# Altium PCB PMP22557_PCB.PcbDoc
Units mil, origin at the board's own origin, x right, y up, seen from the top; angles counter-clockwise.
Board outline 2244.09 x 866.14 mil, 2 copper layers (Top Layer, Bottom Layer), stack 62 mil thick; 30 components, 13 nets, 58 pads, 57 vias.
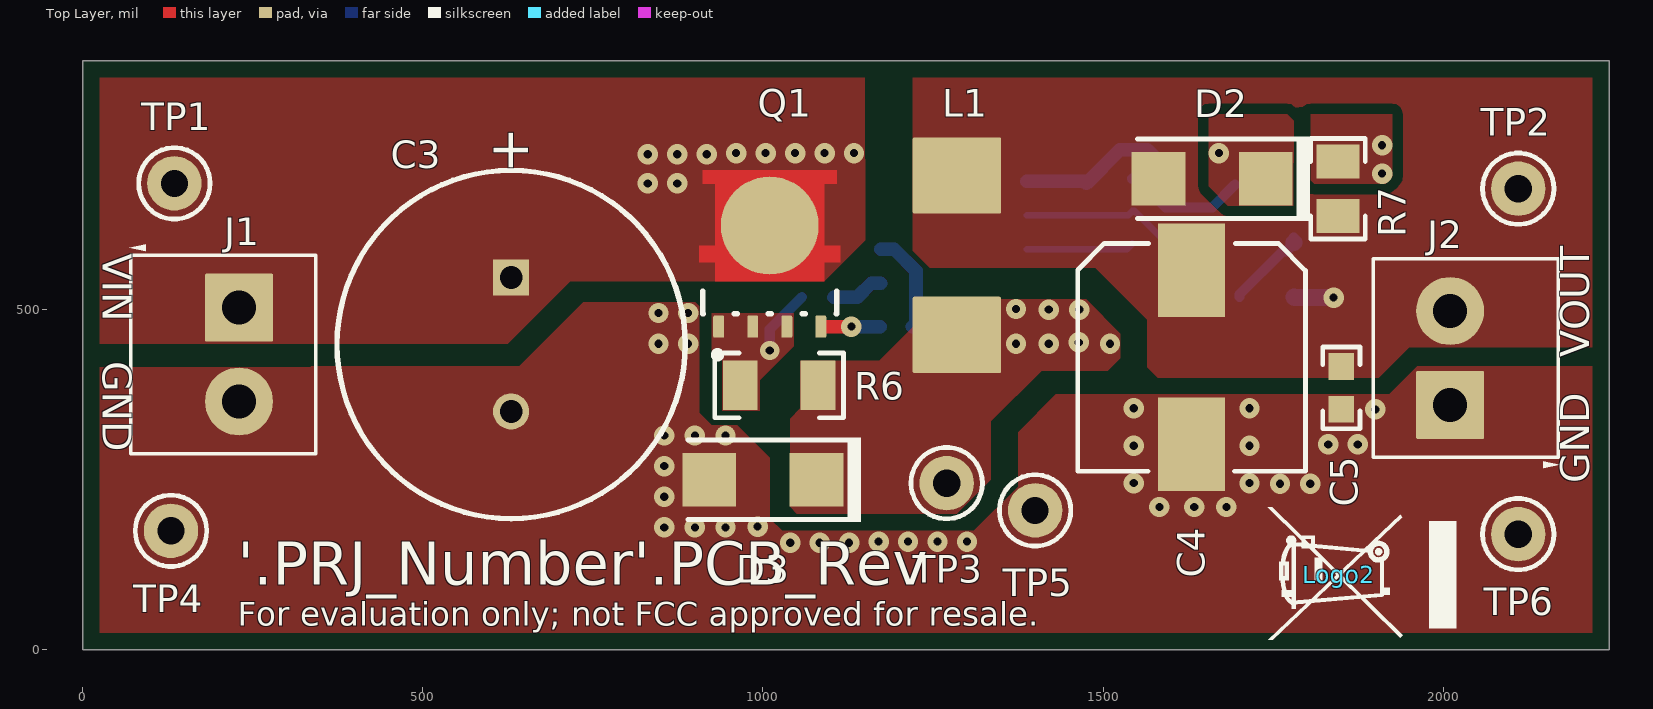
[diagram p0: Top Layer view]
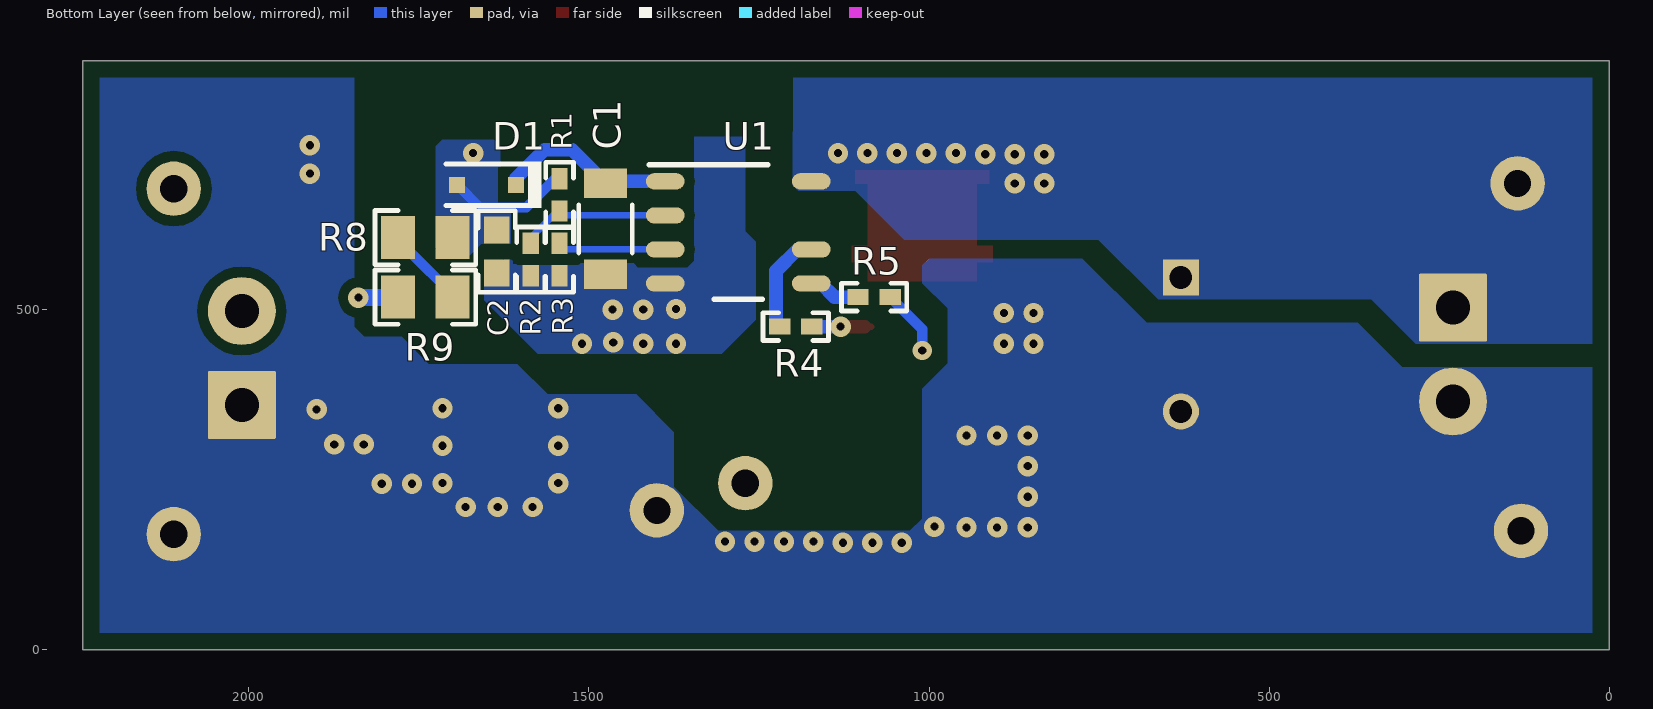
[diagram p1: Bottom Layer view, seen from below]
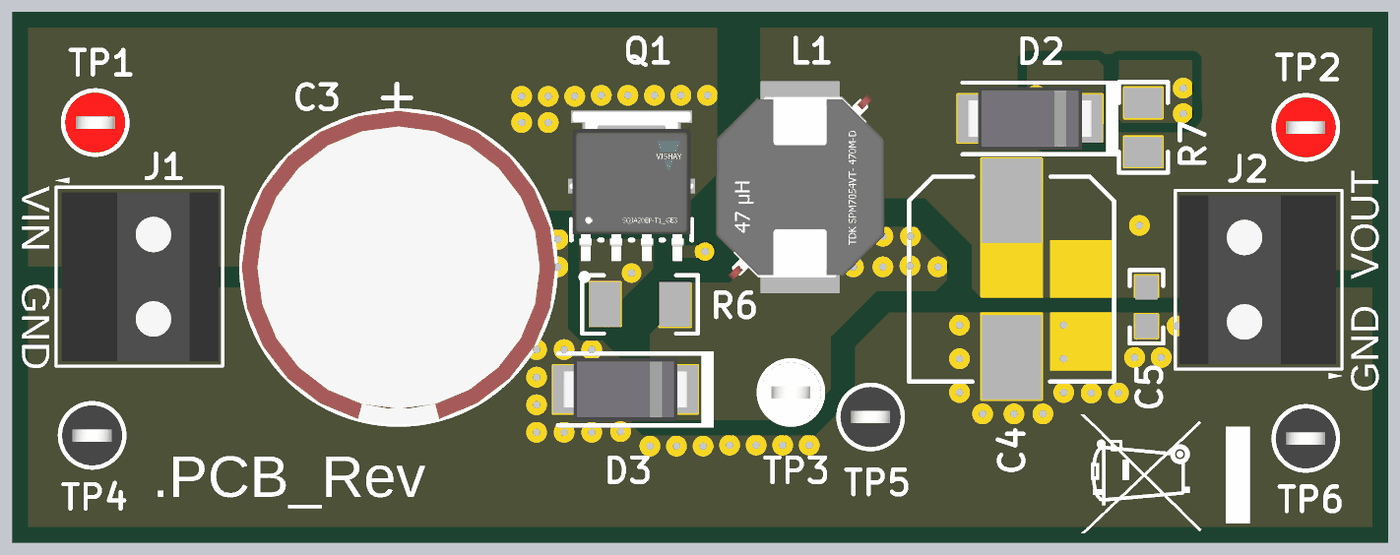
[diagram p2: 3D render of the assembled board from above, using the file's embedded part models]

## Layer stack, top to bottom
Top Solder: solder mask 0.4, Solder Resist, Dk 3.5
Top Layer: signal copper 1.4
Dielectric1: core 59.2, FR-4, Dk 4.8
Bottom Layer: signal copper 1.4
Bottom Solder: solder mask 0.4, Solder Resist, Dk 3.5

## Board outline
0,0 2244.09,0 2244.09,866.14 0,866.14

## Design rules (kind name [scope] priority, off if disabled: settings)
AcuteAngle [All] p1: minimum=4.50000000000000E+0001 checktracksonly=FALSE
AssemblyTestPointUsage [All] p1: valid=2
BoardOutlineClearance BoardOutlineClearance_MountingHoles [OnCopper and InComponentClass('Mounting Holes')] p1: gap=39.37 ignorepadtopadclearanceinfootprint=FALSE
BoardOutlineClearance BoardOutlineClearance_Poly [OnCopper and IsPoly] p2: gap=25 ignorepadtopadclearanceinfootprint=FALSE
BoardOutlineClearance [OnCopper and Not InComponentClass('Logo') and not InComponentClass('FiducialMark') and not InRegion(1000,500,4000,800) and not InPoly] p3: gap=30 ignorepadtopadclearanceinfootprint=FALSE
Clearance Clearance_Keepouts [((IsTrack Or IsArc) And Not InPoly) And IsFree and IsKeepOut vs ((IsTrack Or IsArc) And Not InPoly) And IsFree and IsKeepOut] p1: gap=0 ignorepadtopadclearanceinfootprint=FALSE
Clearance Clearance_Poly [InPolygon] p2: gap=15 ignorepadtopadclearanceinfootprint=TRUE
Clearance Clearance_FiducialMark [IsKeepOut and InComponentClass('FiducialMark') vs IsPad and InComponentClass('FiducialMark')] p3: gap=0 ignorepadtopadclearanceinfootprint=FALSE
Clearance [All] p4: gap=7.87 ignorepadtopadclearanceinfootprint=TRUE
ComponentClearance ComponentClearance_MountingHoles_FiducialMarks [InComponentClass('Mounting Holes') vs InComponentClass('FiducialMark')] p1: gap=50 collisioncheckmode=3 verticalgap=10 showdistances=FALSE
ComponentClearance ComponentClearance_Shunt [InComponentClass('Header') vs InComponentClass('Shunt')] p2: gap=0 collisioncheckmode=3 verticalgap=0 showdistances=FALSE
ComponentClearance ComponentClearance_Logo [InComponentClass('Logo')] p3: gap=50 collisioncheckmode=3 verticalgap=10 showdistances=FALSE
ComponentClearance ComponentClearance_ScrewToNut [(HasFootprint('NY PMS 440 0025 PH')) vs (HasFootprint('Keystone_1902C'))] p4: gap=5 collisioncheckmode=3 verticalgap=10 showdistances=FALSE
ComponentClearance ComponentClearance_MountingHoles [InComponentClass('Mounting Holes')] p5: gap=250 collisioncheckmode=3 verticalgap=100000 showdistances=FALSE
ComponentClearance ComponentClearance_SmallPassives [HasFootprint('0201*') or HasFootprint('0402*') or HasFootprint('0508') or HasFootprint('0603*') or HasFootprint('0612') or HasFootprint('0805*') or HasFootprint('0815*') or HasFootprint('0830*') or HasFootprint('1206*') or HasFootprint('1210*') or HasFootprint('1808*') or HasFootprint('1812*') or HasFootprint('1825*') or HasFootprint('2010*') or HasFootprint('2220*') or HasFootprint('2225*') or HasFootprint('2512*') or HasFootprint('2728*') or HasFootprint('3518*') vs HasFootprint('0201*') or HasFootprint('0402*') or HasFootprint('0508') or HasFootprint('0603*') or HasFootprint('0612') or HasFootprint('0805*') or HasFootprint('0815*') or HasFootprint('0830*') or HasFootprint('1206*') or HasFootprint('1210*') or HasFootprint('1808*') or HasFootprint('1812*') or HasFootprint('1825*') or HasFootprint('2010*') or HasFootprint('2220*') or HasFootprint('2225*') or HasFootprint('2512*') or HasFootprint('2728*') or HasFootprint('3518*')] p6: gap=14.96 collisioncheckmode=3 verticalgap=10 showdistances=FALSE
ComponentClearance ComponentClearance_THtoSMT [IsThruComponent vs IsSMTComponent] p7: gap=30 collisioncheckmode=3 verticalgap=30 showdistances=FALSE
ComponentClearance ComponentClearance_THtoTH [IsThruComponent vs IsThruComponent] p8: gap=30 collisioncheckmode=3 verticalgap=30 showdistances=FALSE
ComponentClearance [All] p9: gap=20 collisioncheckmode=3 verticalgap=10 showdistances=FALSE
DiffPairsRouting [All] p1: maxlimit=100 minlimit=10 mostfreqgap=10 toplayer_minwidth=15 toplayer_maxwidth=15 toplayer_prefwidth=15 bottomlayer_minwidth=15 bottomlayer_maxwidth=15 bottomlayer_prefwidth=15 maxuncoupledlength=1000
FabricationTestPointUsage TestPointUsage [All] p1: valid=2 allowmultiple=FALSE
FabricationTestpoint Testpoint [All] p1: side=3 testpointundercomponent=TRUE minsize=40 maxsize=100 preferedsize=60 minholesize=0 maxholesize=40 preferedholesize=32 testpointgrid=1 allowsidetop=TRUE allowsidebottom=TRUE usegrid=TRUE gridtolerance=0.01
FanoutControl Fanout_LCC [IsLCC] p1: bgadir=Out bgaviamode=Centered fanoutstyle=Auto fanoutdirection=Alternating viagrid=1 // Fanout_LCC (Default Rule)
FanoutControl Fanout_BGA [IsBGA] p2: bgadir=Out bgaviamode=Centered fanoutstyle=Auto fanoutdirection=Alternating viagrid=1 // Fanout_BGA (Default Rule)
FanoutControl Fanout_Default [All] p4: bgadir=Out bgaviamode=Centered fanoutstyle=Auto fanoutdirection=Alternating viagrid=1 // Fanout_Default (Default Rule)
FanoutControl Fanout_Small [(CompPinCount < 5)] p5: bgadir=Out bgaviamode=Centered fanoutstyle=Auto fanoutdirection=OutThenIn viagrid=1 // Fanout_Small (Default Rule)
HoleSize [All] p1: absolutevalues=TRUE maxlimit=251 minlimit=7.87 maxpercent=80.000 minpercent=20.000
MinimumAnnularRing MinimumAnnularRing_ThermalPadVias [IsVia and InAnyComponent] p1: minimumring=5.91
MinimumAnnularRing [All] p2: minimumring=7.87
MinimumSolderMaskSliver MinimumSolderMaskSliver_Logo [InComponentClass('Logo') vs InComponentClass('Logo')] p1: minsoldermaskwidth=0.7
MinimumSolderMaskSliver [All] p2: minsoldermaskwidth=3.94
PlaneClearance [All] p1: clearance=15
PlaneConnect [All] p1: planeconnectstyle=Direct reliefexpansion=10 reliefentries=4 reliefconductorwidth=10 reliefairgap=10
PolygonConnect [All] p1: connectstyle=Direct reliefconductorwidth=10 reliefentries=4 polygonreliefangle="90 Angle" airgapwidth=10
RoutingVias ThermalPadVias [IsVia and InAnyComponent] p1: holewidth=7.87 width=19.68 viastyle="Through Hole" minholewidth=7.87 minwidth=19.68 maxholewidth=30 maxwidth=100
RoutingVias [All] p2: holewidth=16 width=34 viastyle="Through Hole" minholewidth=7.87 minwidth=20 maxholewidth=40 maxwidth=100
SilkToBoardRegionClearance [Not ((IsComment or IsDesignator) And (Hide <> 'False')) and not InRegion(1000,500,4000,800)] p1:
SilkToSilkClearance SilkToSilkClearance_Pb-FreeLogo [(HasFootprint('Pb-Free_Overlay_Medium') OR HasFootprint('Pb-Free_Overlay_Small')) vs (HasFootprint('Pb-Free_Overlay_Medium') OR HasFootprint('Pb-Free_Overlay_Small'))] p1: silktosilkclearance=0
SilkToSilkClearance [All] p2: silktosilkclearance=0
SilkToSolderMaskClearance SilkToComponentPadClearance [(IsPad or IsFill or IsRegion) and InAnycomponent] p1: minsilkscreentomaskgap=0 clearancetoexposedcopper=TRUE
SilkToSolderMaskClearance "Silk to Solder Mask Opening" [All] p2: minsilkscreentomaskgap=0 clearancetoexposedcopper=FALSE
SolderMaskExpansion [All] p1: expansion=1.97
UnRoutedNet [All] p1: checkbadconnections=TRUE
Width [All] p1: maxlimit=100 minlimit=6 preferedwidth=10 checkconnectedcopper=TRUE
13 further rules are at their usual default settings.

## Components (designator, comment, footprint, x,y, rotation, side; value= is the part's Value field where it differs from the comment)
C1 "GCM31CC71E106KA03L" 1206_190 1475.31,618.65 r270 bottom value=10uF
C2 "CGA3E2C0G1H220J080AA" 0603 1635.31,585.46 r270 bottom value=22pF
C3 "UCS2E470MHD1TO" CS_1250x2000 629.92,448.82 r270 top value=33uF
C4 "EEHZA1E221P" SM_RADIAL_8MM 1630,430 r270 top value=220uF
C5 "GCM188R71E105KA64D" 0603 1850,385 r270 top value=1uF
D1 "1N4148WS-HG3-08" SOD-323 1650.31,683.41 r0 bottom value=100V
D2 "ES1D-E3/61T" SMA 1660,692.27 r180 top value=200V
D3 "ES1D-E3/61T" SMA 1000,250 r180 top value=200V
J1 "ED555/2DS" TERM_BLK_ED555-2DS 230,503 r270 top
J2 "ED555/2DS" TERM_BLK_ED555-2DS 2010,360 r90 top
L1 "SPM7054VT-470M-D" "FP-SPM7054VT- 470M-D_STM_7MM5_7MM0-0" 1285,580 r90 top
Logo1 "FCC disclaimer" FCC_disclaimer 5026.49,700.25 r90 top
Logo2 "WEEE logo" WEEE_Minimum 1846.46,110.24 r90 top
Q1 "SQJA20EP-T1_GE3" "FP-SQJA20EP-T1_GE3_PowerPAK SO-8L Single-MFG" 1010,581.89 r0 top
R1 "CRCW0402100KFKED" 0402 1542.83,668.65 r90 bottom value=100k
R2 "CRCW040249K9FKED" 0402 1585.31,573.65 r90 bottom value=49.9k
R3 "CRCW0402100KFKED" 0402 1542.83,573.65 r270 bottom value=100k
R4 "ERJ-2GE0R00X" 0402 1195.87,475 r180 bottom value=0
R5 "CRCW04022K00FKED" 0402 1080.83,518.41 r0 bottom value=2.00k
R6 "ERJ-8RQFR33V" 1206 1023.74,388.7 r0 top value=0.33
R7 "ERJ-6ENF1002V" 0805_HV 1845,677.71 r270 top value=10.0k
R8 "CRCW080561K9FKEA" 0805_HV 1740.16,605.85 r180 bottom value=61.9k
R9 "CRCW080561K9FKEA" 0805_HV 1740.16,518.41 r180 bottom value=61.9k
TP1 "5000" Keystone5000 135,685.58 r90 top
TP2 "5000" Keystone5000 2110,677.71 r90 top
TP3 "5002" Keystone5002 1270,245 r90 top
TP4 "5001" Keystone5001 130,175 r90 top
TP5 "5001" Keystone5001 1400,205 r90 top
TP6 "5001" Keystone5001 2110,170 r90 top
U1 "UCC28730QDRQ1" D0007A_N 1280.31,613.65 r180 bottom

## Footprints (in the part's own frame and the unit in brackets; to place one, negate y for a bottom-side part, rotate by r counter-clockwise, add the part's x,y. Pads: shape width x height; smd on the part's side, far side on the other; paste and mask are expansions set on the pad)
0402 [mm] "0402 from SM-752 data"
  rect 0.8x0.6 smd: 1(-0.6,0) 2(0.6,0)
  silkscreen extent -1.22,-0.52 1.22,0.52, body extent -0.55,-0.3 0.55,0.3, height 0.6
0603 [mm] "0603 from SM-752 data"
  rect 1x0.95 smd: 1(-0.8,0) 2(0.8,0)
  silkscreen extent -1.52,-0.69 1.52,0.69, body extent -0.87,-0.47 0.87,0.47, height 1
0805_HV [mil] "0805 with 30mil clearance between pads"
  rect 50x63 smd: 1(-40,0) 2(40,0)
  silkscreen extent -74,-40 74,40, body extent -43,-29 43,29, height 57
1206 [mm] "1206 from SM-752 data"
  rect 1.3x1.85 smd: 1(-1.45,0) 2(1.45,0)
  silkscreen extent -2.4,-1.21 2.4,1.21, body extent -1.7,-0.9 1.7,0.9, height 1.35
1206_190 [mm] "1206_190"
  rect 1.1x1.6 smd: 1(-1.7,0) 2(1.7,0)
  silkscreen extent -0.9,-1 0.9,1, body extent -1.75,-0.95 1.75,0.95, height 1.9
CS_1250x2000 [mm] "TH, 2-Leads, Dia 12.5mm, Lead Spacing 5mm"
  rect 1.35x1.35 hole 0.85: 1(-2.5,0)
  round 1.35 hole 0.85: 2(2.5,0)
  silkscreen extent -6.5,-6.5 6.5,6.5, body extent -6.45,-6.49 6.49,6.49, height 21.5
D0007A_N [mm] "SOIC, 7-Leads, Body 4.9x3.9mm, Pitch 1.27mm, IPC Medium Density"
  oval 1.45x0.6 smd: 1(-2.725,1.905) 2(-2.725,0.635) 3(-2.725,-0.635) 4(-2.725,-1.905) 5(2.725,-1.905) 6(2.725,-0.635) 8(2.725,1.905)
  silkscreen extent -3.32,-2.5 1.1,2.52, body extent -3.01,-2.45 3.01,2.45, height 1.75
FCC_disclaimer [mil]
"FP-SPM7054VT- 470M-D_STM_7MM5_7MM0-0" [mm]
  rrect4% 2.85x3.3 smd paste+0 mask+0: 1(-2.975,0) 2(2.975,0)
  body extent -4.5,-3.8 4.5,3.8, height 0.25
"FP-SQJA20EP-T1_GE3_PowerPAK SO-8L Single-MFG" [mm]
  rrect24% 0.41x0.82 smd paste+0 mask+0: 1(-1.905,-2.715) 2(-0.635,-2.715) 3(0.635,-2.715) 4(1.905,-2.715)
  round 3.655 smd paste+0 mask+0: 5(0,1.061)
  Top Layer region: 0,-1.015 -2.03,-1.015 -2.03,-0.305 -2.625,-0.305 -2.625,0.305 -2.03,0.305 -2.03,2.615 -2.5,2.615 -2.5,3.125 2.5,3.125 2.5,2.615 2.03,2.615 2.03,0.305 2.625,0.305 2.625,-0.305 2.03,-0.305 2.03,-1.015
  silkscreen extent -2.5,-3.89 2.5,-1.39, body extent -2.73,-3.22 2.73,3.23, height 0.25
Keystone5000 [mil] "For Keystone 500x miniature loop terminals"
  round 80 hole 40: 1(0,0)
  silkscreen extent -52,-52 52,52, body extent -49,-49 49,49, height 182
Keystone5001 [mil] "For Keystone 500x miniature loop terminals"
  round 80 hole 40: 1(0,0)
  silkscreen extent -52,-52 52,52, body extent -49,-49 49,49, height 182
Keystone5002 [mil] "For Keystone 500x miniature loop terminals"
  round 80 hole 40: 1(0,0)
  silkscreen extent -52,-52 52,52, body extent -49,-49 49,49, height 182
SM_RADIAL_8MM [mm] "Nichicon 8x10"
  rect 3.5x2.5 smd: 1(-3.25,0) 2(3.25,0)
  silkscreen extent -4.25,-4.25 4.25,4.25, body extent -4.25,-4.25 4.25,4.25, height 10.5
SMA [mm] "Molded Diode, 2-Leads, Body 4.3x2.6mm, IPC Medium Density, based on OnSemi component dimensions and land pattern"
  rect 2x2 smd: 1(-2,0) 2(2,0)
  silkscreen extent -3.66,-1.57 2.79,1.57, body extent -2.6,-1.3 2.6,1.3, height 2.42
SOD-323 [mm] "NXP recommended land pattern"
  rect 0.6x0.6 smd paste-0.05: 1(-1.1,0) 2(1.1,0)
  silkscreen extent -2.06,-0.86 1.53,0.86, body extent -1.3,-0.67 1.3,0.68, height 1.1
TERM_BLK_ED555-2DS [mil]
  rrect4% 100x100 hole 50: 1(0,0)
  round 100 hole 50: 2(138,0)
  silkscreen extent -93,-161 215,113, body extent -69,-150 207,106, height 323
WEEE_Minimum [mil] "WEEElie bin"
  silkscreen extent -95,-172 99,104

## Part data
C1: library part CMP-0008807-2, "CAP, CERM, 10 uF, 25 V, +/- 10%, X7S, AEC-Q200 Grade 1, 1206_190", Cap_Case=1206, Manufacturer=MuRata, Supplier Part Number 1=490-12661-1-ND, TempCo=X7S, Tolerance_%=10%, Value1=Unknown, Value2=25V, ValueDisplayed=10uF
C2: library part CMP-0007071-4, "CAP, CERM, 22 pF, 50 V, +/- 5%, C0G/NP0, AEC-Q200 Grade 1, 0603", Cap_Case=0603, Manufacturer=TDK, Supplier Part Number 1=445-5632-1-ND, TempCo=C0G/NP0, Tolerance_%=5%, Value1=Unknown, Value2=50V, ValueDisplayed=22pF
C3: library part CMP-0010238-2, "CAP, AL, 33 uF, 200 V, +/- 20%, TH", Cap_Case=12.5x20mm, Manufacturer=Nichicon, Supplier Part Number 1=493-13244-1-ND, Tolerance_%=20%, Value1=Unknown, Value2=200V, ValueDisplayed=33uF
C4: library part CMP-0012571-3, "CAP, Polymer Hybrid, 220 uF, 25 V, +/- 20%, 27 ohm, 8x10 SMD", Manufacturer=Panasonic, Supplier Part Number 1=P15437CT-ND, Tolerance_%=20%, Value1="27 ohm", Value2=25V, ValueDisplayed=220uF
C5: library part CMP-0007139-4, "CAP, CERM, 1 uF, 25 V, +/- 10%, X7R, AEC-Q200 Grade 1, 0603", Cap_Case=0603, Manufacturer=MuRata, Supplier Part Number 1=490-10673-1-ND, TempCo=X7R, Tolerance_%=10%, Value1=Unknown, Value2=25V, ValueDisplayed=1uF
D1: library part CMP-0860225-1, "Diode, Switching, 100 V, 150 A, AEC-Q101, SOD-323", Manufacturer=Vishay-Semiconductor, Value1=150A, Value2=1.2V
D2 D3: library part CMP-0082147-2, "Diode, Ultrafast, 200 V, 1 A, AEC-Q101, SMA", Manufacturer=Vishay-Semiconductor, Value1=1A, Value2=0.92V
J1 J2: library part CMP-0074913-1, "Terminal Block, 3.5mm Pitch, 2x1, TH", Color=Grey, Current_A=6A, Manufacturer="On-Shore Technology", Supplier Part Number 1=ED1514-ND, Voltage_V=150V
L1: library part CMP-0088010-1, "Inductor, Shielded, Metal, 47 µH, 2.5 Arms, 0.162 ohm, AEC-Q200, SMD", Manufacturer=TDK, Supplier Part Number 1=445-181900-1-ND
Logo1: library part CMP-0074847-1, "FCC_disclaimer"
Logo2: library part CMP-0074769-1
Q1: library part CMP-0087405-1, "MOSFET N-CH 200V PWRPAK SO-8L", Manufacturer=Vishay
R1 R3: library part CMP-0025950-3, "RES, 100 k, 1%, 0.063 W, AEC-Q200 Grade 0, 0402", Manufacturer=Vishay-Dale, Power_W=63mW, Supplier Part Number 1=541-100KLCT-ND, TempCo="100 ppm/C", Tolerance_%=1%, Value2=0.063W, Value_Code=100k
R2: library part CMP-0026403-2, "RES, 49.9 k, 1%, 0.063 W, AEC-Q200 Grade 0, 0402", Manufacturer=Vishay-Dale, Power_W=63mW, Supplier Part Number 1=541-49.9KLCT-ND, TempCo="100 ppm/C", Tolerance_%=1%, Value2=0.063W, Value_Code=49k9, ValueDisplayed=49.9k
R4: library part CMP-0026992-3, "RES, 0, 5%, 0.1 W, AEC-Q200 Grade 0, 0402", Manufacturer=Panasonic, Power_W=100mW, Supplier Part Number 1=P0.0JCT-ND, TempCo="600 ppm/C", Tolerance_%=5%, Value2=0.1W, Value_Code=0000, ValueDisplayed=0
R5: library part CMP-0026227-2, "RES, 2.00 k, 1%, 0.063 W, AEC-Q200 Grade 0, 0402", Manufacturer=Vishay-Dale, Power_W=63mW, Supplier Part Number 1=541-2.00KLCT-ND, TempCo="100 ppm/C", Tolerance_%=1%, Value2=0.063W, Value_Code=2k00, ValueDisplayed=2.00k
R6: library part CMP-0017788-3, "RES, 0.33, 1%, 0.25 W, AEC-Q200 Grade 0, 1206", Manufacturer=Panasonic, Power_W=250mW, Supplier Part Number 1=P.33RCT-ND, TempCo="250 ppm/C", Tolerance_%=1%, Value2=0.25W, Value_Code=R330, ValueDisplayed=0.33
R7: library part CMP-0021520-3, "RES, 10.0 k, 1%, 0.125 W, AEC-Q200 Grade 0, 0805", Manufacturer=Panasonic, Power_W=125mW, Supplier Part Number 1=P10.0KCCT-ND, TempCo="100 ppm/C", Tolerance_%=1%, Value2=0.125W, Value_Code=10k0, ValueDisplayed=10.0k
R8 R9: library part CMP-0021371-3, "RES, 61.9 k, 1%, 0.125 W, AEC-Q200 Grade 0, 0805", Manufacturer=Vishay-Dale, Power_W=125mW, Supplier Part Number 1=541-61.9KCCT-ND, TempCo="100 ppm/C", Tolerance_%=1%, Value2=0.125W, Value_Code=61k9, ValueDisplayed=61.9k
TP1 TP2: library part CMP-0055137-1, "Test Point, Miniature, Red, TH", Color=Red, Manufacturer=Keystone, Supplier Part Number 1=36-5000-ND
TP3: library part CMP-0055139-1, "Test Point, Miniature, White, TH", Color=White, Manufacturer=Keystone, Supplier Part Number 1=36-5002-ND
TP4 TP5 TP6: library part CMP-0055138-1, "Test Point, Miniature, Black, TH", Color=Black, Manufacturer=Keystone, Supplier Part Number 1=36-5001-ND
U1: library part CMP-0065056-3, "Zero Standby PSR Flyback Controller with CVCC and Wake-Up Monitoring, Automotive, D0007A (SOIC-7)", Alternate Manufacturer="Texas Instruments"

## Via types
v1: diameter 30, hole 12, Top Layer to Bottom Layer, 56 vias
v2: diameter 28, hole 12, Top Layer to Bottom Layer, 1 vias

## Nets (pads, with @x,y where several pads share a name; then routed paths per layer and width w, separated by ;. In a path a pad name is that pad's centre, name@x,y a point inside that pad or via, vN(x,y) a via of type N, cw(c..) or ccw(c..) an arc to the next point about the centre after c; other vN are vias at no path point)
GND: C3.2 C4.2 C5.2 D3.2 J1.2 J2.1 R7.1 TP4.1 TP5.1 TP6.1
  other v1: 1040,157.48 1083.31,157.48 1126.61,157.48 1169.92,159.13 1213.23,159.13 1256.54,159.13 1299.84,159.13 855,180 900,180 945,180 992.13,181.1 1582.68,210 1633.86,210 1681.1,210 855,225 1759.84,244.09 1804.31,244.09 1545,245 1715,245 855,270 1545,300 1715,300 1830.71,302.05 1874.02,302.05 855,315 900,315 945,315 1900,353.5 1545,355 1715,355 846.46,450 890,450 846.46,495.13 890,495.13 1910,700 1910,741.71
NetC1_1: C1.1 D1.1 U1.1 | length 268.1
  Bottom Layer w20: U1.1 1472.24,688.65 C1.1 1524.73,735 1565,735 1607.01,692.99 D1.1
NetC1_2: C1.2 C2.2 D3.1 L1.1 R2.1 R3.2 R6.2 TP3.1 U1.4
  other v1: 1371.85,450 1420,450 1510,450 1464.13,451.84 1420,500 1465,500 1371.85,500.91
NetC2_1: C2.1 D1.2 D2.1 R1.2 R8.2 | length 182
  Bottom Layer w15: R1.2 1549.7,692.27 1591.79,650.18 1660.39,650.18 D1.2
  other v1: 1670,730
NetC3_1: C3.1 J1.1 Q1.5 TP1.1 U1.8
  other v1: 830.71,685.58 874.02,685.58 830.71,728.35 874.02,728.35 917.32,728.35 960.63,730 1003.94,730 1047.24,730 1090.55,730 1133.86,730
NetC4_1: C4.1 C5.1 D2.2 J2.2 L1.2 R7.2 R9.1 TP2.1 | length 58.7
  Bottom Layer w25: R9.1 1780.85,517.72 v1(1838.58,517.72)
NetQ1_1: Q1.1 Q1.2 Q1.3 R5.1 R6.1 | length 98
  Bottom Layer w15: v2(1010,439.98) 1010,471.21 R5.1
NetQ1_4: Q1.4 R4.2 | length 87.2
  Top Layer w10: Q1.4 1094.61,475
  Top Layer w20: 1094.61,475 v1(1130,475)
  Bottom Layer w20: v1(1130,475) R4.2
NetR1_1: R1.1 R2.2 U1.2 | length 225.2
  Bottom Layer w10: U1.2 1536.46,638.65 R1.1 1546.14,645.03 1585.31,605.85 R2.2
NetR3_1: R3.1 U1.3 | length 158.8
  Bottom Layer w10: U1.3 1534.21,588.65 R3.1
NetR4_1: R4.1 U1.6 | length 149.2
  Bottom Layer w20: U1.6 1193.11,588.65 1225,556.76 1225,480.51 R4.1
NetR5_2: R5.2 U1.5 | length 77
  Bottom Layer w20: R5.2 1138.97,518.41 1159.21,538.65 U1.5
NetR8_1: R8.1 R9.2 | length 123.7
  Bottom Layer w15: R9.2 1700.16,522.35 1763.75,585.94 1769.01,585.94 1780.16,597.09 R8.1

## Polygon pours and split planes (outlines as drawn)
GND on Bottom Layer "BOTTOM_LAYER_GND_P036" (solid, remove dead copper, pour order 36): 0,415 304.49,415 370,480.51 680.25,480.51 774.74,575 1000,575 1010,565 1010,539.02 972.75,501.77 972.75,420.95 1010,383.7 1010,193 1028,175 1310,175 1375,240 1375,320 1430.6,375.6 1560.6,375.6 1605,420 1735,420 1775,460 1830,460 1845,475 1845,866.14 2244.09,866.14 2244.09,0 0,0
NetC1_2 on Bottom Layer "BOTTOM_LAYER_NETC1_2_P032" (solid, remove dead copper, pour order 32): 1270,754.27 1270,615 1255,600 1255,485 1305,435 1575,435 1654.02,514.02 1654.02,570 1628.65,570 1625,573.65 1613.65,573.65 1605,565 1515.19,565 1511.93,568.26 1434.24,568.26 1427.82,561.84 1355.21,561.84 1345,572.05 1345,754.27
NetC2_1 on Bottom Layer "BOTTOM_LAYER_NETC2_1_P020" (solid, remove dead copper, pour order 20): 1675,580 1658.28,596.72 1615.55,596.72 1615,597.27 1615,650.18 1630,665.18 1630,741.08 1638.92,750 1715.13,750 1725,740.13 1725,590 1715,580
NetC3_1 on Bottom Layer "BOTTOM_LAYER_NETC3_1_P010" (solid, remove dead copper, pour order 10): 0,866.14 1199.75,866.14 1200.33,680.33 1195,675 1108.1,675 1036.14,603.04 751.08,603.04 663.04,515 350,515 285,450 0,450
GND on Top Layer "TOP_LAYER_GND_P034" (solid, remove dead copper, pour order 34): 0,415 335,415 336.5,416.5 641.5,416.5 735.87,510.87 900.76,510.87 906.63,505 906.63,348.37 925,330 962.32,330 1010,282.31 1010,193 1028,175 1310,175 1375,240 1375,320 1430.6,375.6 1920.6,375.6 1961.5,416.5 2245,416.5 2244.09,415.59 2244.09,0 0,0
GND on Top Layer "TOP_LAYER_GND_P008" (solid, remove dead copper, pour order 8): 1805,690 1805,787.4 1925,787.4 1925.13,694.97 1915,684.84 1809.89,685.02
NetC2_1 on Top Layer "TOP_LAYER_NETC2_1_P006" (solid, remove dead copper, pour order 6): 1779.7,652.91 1683.4,652.91 1655,681.31 1655,787.4 1779.48,787.4 1780,786.88
NetC1_2 on Top Layer "TOP_LAYER_NETC1_2_P024" (solid, remove dead copper, pour order 24): 1171.22,425 1221.22,475 1221.22,491.35 1245,515.13 1474.79,515.13 1525.13,464.79 1525.13,428.83 1506.76,410.46 1409.87,410.46 1334.4,335 1171.22,335
NetC4_1 on Top Layer "TOP_LAYER_NETC4_1_P018" (solid, remove dead copper, pour order 18): 1220,866.14 1220,586.84 1245,561.84 1488.29,561.84 1565,485.13 1565,415.51 1580.51,400 1905,400 1950,445 2244.09,445 2244.09,866.14
NetC1_2 on Top Layer "TOP_LAYER_NETC1_2_P016" (solid, remove dead copper, pour order 16): 1055,425 1055,355 1040,340 1040,210 1050,200 1285,200 1335,250 1335,475 1221.22,475 1171.22,425
NetC3_1 on Top Layer "TOP_LAYER_NETC3_1_P014" (solid, remove dead copper, pour order 14): 0,866.14 1149.65,865.82 1150.25,602.24 1089.94,541.93 716.93,541.93 625,450 0,450
NetQ1_1 on Top Layer "TOP_LAYER_NETQ1_1_P012" (solid, remove dead copper, pour order 12): 1045,495 925,495 925,440 940,425 940,351.57 995,351.57 995,396.57 1045,446.57

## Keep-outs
Keep-Out Layer:
  text ".Layer_Name" at 577,-858.49 h60

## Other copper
Top Layer:
  text ".Layer_Name" at 577,-858.49 h60
Bottom Layer:
  text ".Layer_Name" at 577,-858.49 h60

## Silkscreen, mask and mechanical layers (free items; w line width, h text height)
Top Overlay:
  text "VIN" at 15.75,581.89 h72.83 r270
  text "VOUT" at 2228.35,430 h72.83 r90
  text "GND" at 15.75,424.13 h72.83 r270
  text "GND" at 2228.35,245 h72.83 r90
  text "'.PRJ_Number'.PCB_Rev" at 228.35,74.8 h108.27
  text ".Layer_Name" at 577,-858.49 h60
Bottom Overlay:
  text ".Layer_Name" at 577,-858.49 h60
Top Paste:
  text ".Layer_Name" at 577,-858.49 h60
Bottom Paste:
  text ".Layer_Name" at 577,-858.49 h60
Top Solder:
  rectangle: 1578.66,280.75 1681.02,375.62
  rectangle: 1692.83,280.75 1795.2,375.6
  rectangle: 1692.83,400 1795.2,493.9
  rectangle: 1578.74,400 1681.1,493.9
  text ".Layer_Name" at 577,-858.49 h60
  text ".Layer_Name" at 577,-858.49 h60
Bottom Solder:
  rectangle: 908.82,599.23 988.82,659.45
  rectangle: 822.83,599.23 902.83,659.45
  rectangle: 822.83,517.72 902.83,577.94
  rectangle: 908.82,517.72 988.82,577.94
  text ".Layer_Name" at 577,-858.49 h60
Drill Guide:
  text ".Layer_Name" at 577,-858.49 h60
M1 Board Outline:
  the board outline again, w8
  text ".Layer_Name" at 577,-858.49 h60
M2 Board Dimensions:
  rectangle: 0,-275 125,-150
  rectangle: 125,-400 500,-275
  lines w7: 0,-275 1000,-275 ; 125,-400 125,-150 ; 250,-400 250,-150 ; 500,-400 500,-150 ; 750,-400 750,-150 ; 0,-400 1000,-400 1000,-150 0,-150 0,-400
  text ".Layer_Name" at 577,-858.49 h60
M3 3D STEP Top:
  text ".Layer_Name" at 577,-858.49 h60
M4 3D STEP Bottom:
  text ".Layer_Name" at 577,-858.49 h60
M5 Assembly Top:
  lines w10: -292,-930.17 6308,-930.17 ; -292,-726.83 6310,-726.83 ; -292,-523.5 -292,-1133.5 3713,-1133.5 6310,-1133.5 6310,-523.5 -291.5,-523.5 -291.5,-1133.5 1284,-1133.5 ; 2173,-1133.5 2173,-523.5 ; 3440,-726.83 3440,-523.5 ; 4280,-726.83 4280,-523.5 ; 4902,-1140 4902,-937.17
  text "PMP22557A" at 228.35,74.8 h110
  text "COMPONENTS MARKED 'DNP' SHOULD NOT BE POPULATED." at 1153.5,-318.5 h60
  text "ASSEMBLY VARIANT:" at 1153,-434 h60
  text ".VariantName" at 2189,-434 h60
  text "PCB VIEWED FROM TOP SIDE" at -228.5,-655.67 h60
  text "BOARD #:" at 2248,-655.67 h60
  text ".PRJ_Number" at 2793.5,-655.67 h60
  text "REV:" at 3638,-655.67 h60
  text ".PCB_Rev" at 3929.5,-655.67 h60
  text "SVN REV:" at 4476,-655.67 h60
  text ".VersionControl_RevNumber" at 4982,-655.67 h60
  text "TID #:" at 2248,-859 h60
  text ".TID" at 2793.5,-859 h60
  text "PLOT NAME =" at -228.5,-1064.34 h60
  text ".plot_File_Name" at 577,-1064.34 h60
  text "GENERATED    :" at 2250,-1064.34 h60
  text ".Print_Date" at 3119.5,-1064.34 h60
  text ".Print_Time" at 3848.5,-1064.34 h60
  text "TEXAS INSTRUMENTS" at 5113,-1064.34 h60
M6 Assembly Bottom:
  lines w10: -292.5,-727.33 6309.5,-727.33 ; -290.5,-930.67 6309.5,-930.67 ; 1115.5,-1140.5 1115.5,-937.67 ; 1737.5,-727.33 1737.5,-524 ; 2577.5,-727.33 2577.5,-524 ; 3844.5,-1134 3844.5,-524 ; 4733.5,-1134 6309,-1134 6309,-524 -292.5,-524 -292.5,-1134 2304.5,-1134 6309.5,-1134 6309.5,-524
  text "COMPONENTS MARKED 'DNP' SHOULD NOT BE POPULATED." at 6102,-318 h60
  text ".VariantName" at 5058,-434 h60
  text "ASSEMBLY VARIANT:" at 6097,-434 h60
  text ".VersionControl_RevNumber" at 1035.5,-656.17 h60
  text "SVN REV:" at 1541.5,-656.17 h60
  text ".PCB_Rev" at 2088,-656.17 h60
  text "REV:" at 2379.5,-656.17 h60
  text ".PRJ_Number" at 3224,-656.17 h60
  text "BOARD #:" at 3769.5,-656.17 h60
  text "PCB VIEWED FROM BOTTOM SIDE" at 6246,-656.17 h60
  text ".TID" at 3224,-859.5 h60
  text "TID #:" at 3769.5,-859.5 h60
  text "TEXAS INSTRUMENTS" at 904.5,-1064.84 h60
  text ".Print_Time" at 2169,-1064.84 h60
  text ".Print_Date" at 2898,-1064.84 h60
  text "GENERATED    :" at 3767.5,-1064.84 h60
  text ".plot_File_Name" at 5440.5,-1064.84 h60
  text "PLOT NAME =" at 6246,-1064.84 h60
M9 Title Sheet:
  drawing of 57 lines, arcs and shapes, not listed
  text "1" at 739.84,8036.5 h70
  text "2" at 3235.5,8036.5 h70
  text "3" at 5724.84,8036.5 h70
  text "4" at 8231.51,8036.5 h70
  text "5" at 10730.5,8036.5 h70
  text "6" at 13235.5,8036.5 h70
  text "A" at -416.5,6893.5 h70
  text "A" at 14383.5,6893.5 h70
  text "B" at -416.5,4513.5 h70
  text "B" at 14383.5,4513.5 h70
  text "C" at -416.5,2138.5 h70
  text "C" at 14383.5,2138.5 h70
  text "PROJECT TITLE:" at 11343.5,277.5 h45
  text ".PRJ_Title" at 11393.5,144.17 h70
  text "DESIGNED FOR:" at 11343.5,-23.5 h45
  text ".PRJ_Customer" at 11393.5,-163.5 h70
  text "D" at -416.5,-231.5 h70
  text "D" at 14383.5,-231.5 h70
  text "FILE NAME:" at 11343.5,-323.5 h45
  text ".PCB_File_Name_No_Path" at 11393.5,-443.5 h70
  text "Texas Instruments (TI) and/or its licensors do not warrant the accuracy or completeness of this specification" at 6374,-605.34 h45
  text "ENGINEER:" at 11343.5,-613.5 h45
  text "LAYOUT BY:" at 12848.5,-613.5 h45
  text "or any information contained therein. TI and/or its licensors do not warrant that this design will meet" at 6329.01,-718 h45
  text ".PRJ_Engineer" at 11393.5,-768.49 h70
  text ".PCB_Layout" at 12899,-768.49 h70
  text "the specifications, will be suitable for your application or fit for any particular purpose, or will operate in" at 6329.01,-830.67 h45
  text ".Layer_Name" at 577,-858.49 h60
  text "ALTIUM DESIGNER VERSION:" at 12848.5,-923.5 h45
  text "an implementation. TI and/or its licensors do not warrant that the design is production worthy. You should" at 6329.01,-943.33 h45
  text "completely validate and test your design implementation to confirm the system functionality for your application." at 6374,-1056 h45
  text ".print_Scale" at 11393.5,-1056.83 h70
  text ".Application_BuildNumber" at 12899,-1056.83 h70
  text "1" at 739.84,-1263.5 h70
  text "2" at 3235.5,-1263.5 h70
  text "3" at 5724.84,-1263.5 h70
  text "4" at 8231.51,-1263.5 h70
  text "5" at 10730.5,-1263.5 h70
  text "6" at 13235.5,-1263.5 h70
M10 Fab Notes:
  drawing of 189 lines, arcs and shapes, not listed
  text "DESIGN INFORMATION" at 12382.02,6356.17 h60
  text "MIN. TRACK WIDTH:" at 11737.46,6224.05 h60
  text "8" at 12833.7,6224.05 h60
  text "MIL" at 12988.46,6224.05 h60
  text "MIN. CLEARANCE:" at 11737.46,6099.92 h60
  text "0.2" at 12773.7,6099.93 h60
  text "mm" at 12988.46,6099.92 h60
  text "MIN. VIA PAD SIZE:" at 11737.46,5975.8 h60
  text "24" at 12803.71,5975.8 h60
  text "MIL" at 12988.46,5975.8 h60
  text "0.05mm (2MIL)" at 12432.46,5845.9 h60
  text "MINIMUM ANNULAR RING" at 11408.23,5837.67 h60
  text "EXTERNAL" at 13140.46,5837.67 h60
  text "PER" at 11608.23,5727.55 h60
  text "IPC-D-275 CLASS 2 LEVEL C" at 11828.23,5727.54 h60
  text "MIL, HOLES" at 13316.46,5627.07 h60
  text "+/-" at 12924,5618.48 h60
  text "+/-" at 13778,5618.48 h60
  text "REGISTRATION TOLERANCES:" at 11408.23,5617.42 h60
  text "METAL" at 12608,5617.42 h60
  text "5" at 13184.2,5617.42 h60
  text "3" at 14017.2,5617.42 h60
  text "MIL" at 14133.46,5617.42 h60
  text "HOLE SIZE TOLERANCE (UNLESS OTHERWISE SPECIFIED):" at 11408.23,5519.1 h60
  text "+/-" at 13778,5516.23 h60
  text "3" at 14017.2,5515.17 h60
  text "MIL" at 14133.46,5515.17 h60
  text "MATERIAL:" at 11333.46,5377.52 h60
  text "FR-4 High Tg" at 12319.9,5249 h60
  text "X" at 12175.46,5241.01 h60
  text "FR-408" at 11754.46,5236.49 h60
  text "OTHER" at 13242.46,5236.49 h60
  text "62 MIL (1.6mm) +/-10%" at 12074.56,5093.46 h60
  text "X" at 11954.46,5091.01 h60
  text "THICKNESS:" at 11408.23,5085.24 h60
  text "OTHER" at 13359.46,5085.24 h60
  text "TOLERANCE:" at 11408.23,4946.92 h60
  text "X" at 12256.46,4946.92 h60
  text "ANSI IPC-6012 TYPE 3 CLASS 2" at 12434.48,4946.92 h60
  text "OTHER +/-" at 12434.46,4802.73 h60
  text "BOW & TWIST:" at 11408.23,4657.54 h60
  text "X" at 12256.46,4657.54 h60
  text "ANSI IPC-6012 TYPE 3 CLASS 2" at 12434.48,4657.54 h60
  text "OTHER +/-" at 12434.46,4510.85 h60
  text "DRILLING:" at 11333.46,4380.23 h60
  text "NC_DRILL FILES" at 13094.46,4275.04 h60
  text "REFERENCE:" at 11408.23,4271.1 h60
  text "X" at 12065.46,4271.01 h60
  text "AS SHOWN" at 12243.46,4271.1 h60
  text "X" at 12966.46,4271.1 h60
  text "OTHER" at 13392.46,4128.85 h60
  text "PTH COPPER THICKNESS:" at 11407.91,4125.32 h60
  text "X" at 12547.14,4125.32 h60
  text "20-30 um" at 12675.14,4125.32 h60
  text "BOARD FINISH:" at 11333.46,3977.73 h60
  text "SILKSCREEN:" at 11488.68,3867.6 h60
  text "X" at 12446.46,3867.6 h60
  text "TOP" at 12563.46,3867.6 h60
  text "X" at 12956.46,3867.6 h60
  text "BOTTOM" at 13074.46,3867.6 h60
  text "SILKSCREEN COLOR:" at 11488.68,3712.41 h60
  text "X" at 12445.46,3712.41 h60
  text "WHITE" at 12563.46,3712.41 h60
  text "OTHER" at 13074.46,3712.41 h60
  text "X" at 12576.46,3568.96 h60
  text "GREEN" at 12694.46,3568.96 h60
  text "OTHER" at 13312.46,3568.96 h60
  text "SOLDER RESIST COLOR:" at 11488.68,3562.1 h60
  text "X" at 12576.46,3414.71 h60
  text "MATTE" at 12694.46,3414.71 h60
  text "SEMI-GLOSS" at 13312,3414.07 h60
  text "IMMERSION GOLD (ENIG)" at 12394.46,3241.94 h60
  text "ENEPIG" at 13732,3234.72 h60
  text "SURFACE FINISH:" at 11333.46,3233.72 h60
  text "X" at 12216.46,3233.72 h60
  text "IMM. TIN/SILVER OR EQUIV" at 11663,3096.4 h60
  text "OTHER" at 13094.46,3092.47 h60
  text "ARRAY/PANEL:" at 11333.46,2937.09 h60
  text "CUT AND TRIM PER M1 BOARD OUTLINE" at 12394.46,2928.87 h60
  text "N.C. ROUTE" at 12394.46,2792.9 h60
  text "X" at 13082.46,2792.9 h60
  text "V. SCORE" at 13260.46,2792.9 h60
  text "CERTIFICATION:" at 11333.46,2663.77 h60
  text "MATERIALS AND WORKMANSHIP FOR ALL PCBS" at 12058.46,2663.77 h60
  text "TO MEET OR EXCEED THE REQUIREMENTS OF:" at 12058.46,2569.71 h60
  text "X" at 11695.97,2441.08 h60
  text "ANSI IPC-A-600F CLASS ->" at 11823.96,2441.08 h60
  text "X" at 13471.97,2441.08 h60
  text "2" at 13581.96,2441.08 h60
  text "1" at 13266.96,2439.58 h60
  text "3" at 13935.96,2439.58 h60
  text "X" at 12507.97,2293.39 h60
  text "RoHS" at 12635.96,2293.39 h60
  text "OTHER" at 13280.36,2293.39 h60
  text "PER ORDER" at 13677.42,2293.39 h60
  text "ALL BOARDS MUST MEET OR EXCEED UL94-V0 REQUIREMENTS." at 11361,2139.57 h60
  text "PCB MUST BEAR THE UL94V-0 UL REGISTERED MATERIAL ID NUMBER" at 11361,2023.5 h60
  text "ADDITIONAL REQUIREMENTS:" at 11333.46,1854.08 h60
  text "MICROSECTION:" at 11408.23,1746.95 h60
  text "YES" at 12313.96,1746.95 h60
  text "REQUIRED" at 13175.46,1602.62 h60
  text "BARE BOARD ELEC. TEST:" at 11408.23,1599.76 h60
  text "NONE" at 12713.96,1599.76 h60
  text "X" at 13057.46,1599.76 h60
  text "PER ORDER" at 13767.46,1599.76 h60
  text "XX MIL VIAS REQUIRE NON-CONDUCTIVE FILL AND PLANARIZE" at 11576.38,1394.82 h59
  text "XX MIL VIAS REQUIRE CONDUCTIVE FILL AND PLANARIZE" at 11584.38,1290.84 h60
  text "OUTER XX MIL TRACES REQUIRE 50 OHM SINGLE-ENDED IMPEDANCE" at 11583.39,1127.46 h58
  text "LAYER 2 & 3 (INNER LAYERS) XX MIL WIDE, XX MIL SPACE / TRACES REQUIRE 100 OHM DIFFERENTIAL IMPEDANCE" at 11575.39,891.74 h60
  text ".Layer_Name" at 577,-858.49 h60
M11 Gerber Information:
  lines w10: -292,-930.17 6308,-930.17 ; -292,-726.83 6310,-726.83 ; -292,-523.5 -292,-1133.5 3713,-1133.5 6310,-1133.5 6310,-523.5 -291.5,-523.5 -291.5,-1133.5 1284,-1133.5 ; 2173,-1133.5 2173,-523.5 ; 3440,-726.83 3440,-523.5 ; 4280,-726.83 4280,-523.5 ; 4902,-1140 4902,-937.17
  text "ALL ARTWORK VIEWED FROM TOP SIDE" at -228.5,-655.67 h60
  text "BOARD #:" at 2248,-655.67 h60
  text ".PRJ_Number" at 2793.5,-655.67 h60
  text "REV:" at 3638,-655.67 h60
  text ".PCB_Rev" at 3929.5,-655.67 h60
  text "SVN REV:" at 4476,-655.67 h60
  text ".VersionControl_RevNumber" at 4982,-655.67 h60
  text "LAYER NAME =" at -228.5,-858.49 h60
  text "TID #:" at 2248,-859 h60
  text ".TID" at 2793.5,-859 h60
  text "PLOT NAME =" at -228.5,-1064.34 h60
  text ".plot_File_Name" at 577,-1064.34 h60
  text "GENERATED    :" at 2250,-1064.34 h60
  text ".Print_Date" at 3119.5,-1064.34 h60
  text ".Print_Time" at 3848.5,-1064.34 h60
  text "TEXAS INSTRUMENTS" at 5113,-1064.34 h60
M12 Stackup:
  drawing of 191 lines, arcs and shapes, not listed
  text "Layer" at 9716.41,7781.81 h60
  text "Name" at 10126.32,7781.81 h60
  text "Material" at 11056.06,7781.81 h60
  text "Thickness" at 11915.83,7781.81 h60
  text "Constant" at 12565.67,7781.81 h60
  text "Board Layer Stack" at 13135.53,7781.81 h60
  text "1" at 9716.41,7661.81 h60
  text "Top Overlay" at 10126.32,7661.81 h60
  text "2" at 9716.41,7541.81 h60
  text "Top Solder" at 10126.32,7541.81 h60
  text "Solder Resist" at 11056.06,7541.81 h60
  text "0.40mil" at 11915.83,7541.81 h60
  text "3.5" at 12565.67,7541.81 h60
  text "3" at 9716.41,7421.81 h60
  text "Top Layer" at 10126.32,7421.81 h60
  text "Copper" at 11056.06,7421.81 h60
  text "1.40mil" at 11915.83,7421.81 h60
  text "4" at 9716.41,7301.81 h60
  text "Dielectric1" at 10126.32,7301.81 h60
  text "FR-4" at 11056.06,7301.81 h60
  text "59.20mil" at 11915.83,7301.81 h60
  text "4.8" at 12565.67,7301.81 h60
  text "5" at 9716.41,7181.81 h60
  text "Bottom Layer" at 10126.32,7181.81 h60
  text "Copper" at 11056.06,7181.81 h60
  text "1.40mil" at 11915.83,7181.81 h60
  text "6" at 9716.41,7061.81 h60
  text "Bottom Solder" at 10126.32,7061.81 h60
  text "Solder Resist" at 11056.06,7061.81 h60
  text "0.40mil" at 11915.83,7061.81 h60
  text "3.5" at 12565.67,7061.81 h60
  text "7" at 9716.41,6941.81 h60
  text "Bottom Overlay" at 10126.32,6941.81 h60
  text ".Layer_Name" at 577,-858.49 h60
M13 Component Bodies Top:
  text ".Layer_Name" at 577,-858.49 h60
M14 Component Bodies Bottom:
  text ".Layer_Name" at 577,-858.49 h60
M15 Courtyards Top:
  text ".Layer_Name" at 577,-858.49 h60
M16 Courtyards Bottom:
  text ".Layer_Name" at 577,-858.49 h60
Drill Drawing:
  circle w10: c3650.56,1497.21 r27.59
  lines w10: 3622.97,1593.79 3678.15,1593.79 3678.15,1648.98 3622.97,1648.98 3622.97,1593.79 ; 3622.97,1773.16 3678.15,1773.16 3650.56,1717.97 3622.97,1773.16 ; 3622.97,1842.14 3650.56,1855.94 3678.15,1842.14 3664.36,1869.74 3678.15,1897.33 3650.56,1883.54 3622.97,1897.33 3636.76,1869.74 3622.97,1842.14
  lines w12: 3572.93,1432.36 6803.45,1432.36 ; 3572.93,1929.07 6803.45,1929.07 ; 3910.79,1308.19 3910.79,2053.24 ; 4242.79,1308.19 4242.79,2053.24 ; 4879.35,1308.19 4879.35,2053.24 ; 5138.45,1308.19 5138.45,2053.24 ; 5513.61,1308.19 5513.61,2053.24 ; 6236.99,1308.19 6236.99,2053.24 ; 3572.93,1308.19 6803.45,1308.19 6803.45,2053.24 3572.93,2053.24 3572.93,1308.19
  text "Symbol" at 3647.43,1966.32 h72
  text "Quantity" at 3948.04,1966.32 h72
  text "Finished Hole Size" at 4280.05,1966.32 h72
  text "Plated" at 4916.6,1966.32 h72
  text "Hole Type" at 5175.71,1966.32 h72
  text "Drill Layer Pair" at 5550.86,1966.32 h72
  text "Hole Tolerance" at 6274.25,1966.32 h72
  text "57" at 3948.04,1842.14 h60
  text "12.00mil (0.305mm)" at 4280.05,1842.14 h60
  text "PTH" at 4916.6,1842.14 h60
  text "Round" at 5175.71,1842.14 h60
  text "Top Layer - Bottom Layer" at 5550.86,1842.14 h60
  text "2" at 3948.04,1717.97 h60
  text "33.47mil (0.850mm)" at 4280.05,1717.97 h60
  text "PTH" at 4916.6,1717.97 h60
  text "Round" at 5175.71,1717.97 h60
  text "Top Layer - Bottom Layer" at 5550.86,1717.97 h60
  text "6" at 3948.04,1593.79 h60
  text "40.00mil (1.016mm)" at 4280.05,1593.79 h60
  text "PTH" at 4916.6,1593.79 h60
  text "Round" at 5175.71,1593.79 h60
  text "Top Layer - Bottom Layer" at 5550.86,1593.79 h60
  text "4" at 3948.04,1469.62 h60
  text "50.00mil (1.270mm)" at 4280.05,1469.62 h60
  text "PTH" at 4916.6,1469.62 h60
  text "Round" at 5175.71,1469.62 h60
  text "Top Layer - Bottom Layer" at 5550.86,1469.62 h60
  text "69 Total" at 3948.04,1345.44 h60
  text ".Layer_Name" at 577,-858.49 h60
M17 Embedded Cavity:
  text ".Layer_Name" at 577,-858.49 h60
M18 Embedded Assembly:
  text ".Layer_Name" at 577,-858.49 h60
M19 Embedded Keepout:
  text ".Layer_Name" at 577,-858.49 h60

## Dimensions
0,-400 to 1000,-400 on M2 Board Dimensions
0,0 to 0,866.14 on M2 Board Dimensions
0,0 to 2244.09,0 on M2 Board Dimensions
